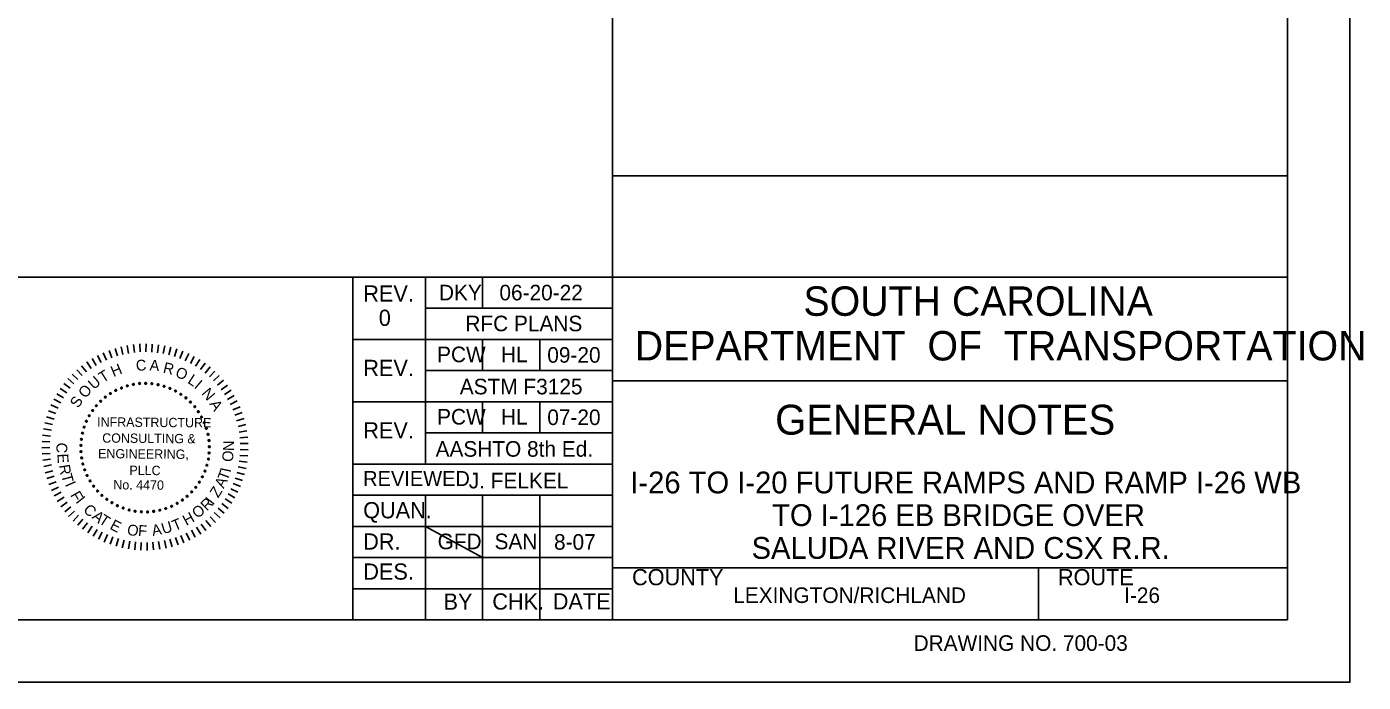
# Model space of a CAD drawing. Extents: x -1.3 to 34.8, y 0.8 to 22.8.
# Drawn here: x 24.06 to 34.78, y 0.82 to 6.08 of the extents above; entities that cross this region are included whole.
import ezdxf

# ---------------------------------------------------------------- set-up
doc = ezdxf.new("R2010")
doc.units = 0
for name, color, linetype in [('BR_BORDER LINES', 7, 'Continuous'), ('BR_TEXT', 7, 'Continuous'), ('Level 31', 7, 'Continuous')]:
    doc.layers.add(name, color=color, linetype=linetype)

msp = doc.modelspace()

# ---------------------------------------------------------------- linework, layer by layer
at = {"layer": 'BR_BORDER LINES'}
for p, q in [((34.177, 1.318), (34.177, 22.318)), ((28.76, 1.318), (28.76, 6.595)), ((28.76, 4.88), (34.177, 4.88)), ((21.311, 4.068), (26.676, 4.068)), ((26.676, 1.318), (26.676, 4.068)), ((26.676, 4.068), (34.177, 4.068)), ((27.26, 4.068), (27.26, 2.568)), ((27.718, 3.818), (27.718, 4.068)), ((27.26, 3.818), (28.76, 3.818)), ((26.676, 3.568), (28.76, 3.568)), ((27.718, 3.318), (27.718, 3.568)), ((28.176, 3.318), (28.176, 3.568)), ((27.26, 3.318), (28.76, 3.318)), ((28.76, 3.235), (28.76, 3.235)), ((28.76, 3.235), (34.177, 3.235)), ((26.676, 3.068), (28.76, 3.068)), ((27.718, 2.818), (27.718, 3.068)), ((28.176, 2.818), (28.176, 3.068)), ((27.26, 2.818), (28.76, 2.818)), ((26.676, 2.568), (28.76, 2.568)), ((26.676, 2.318), (28.76, 2.318)), ((27.26, 2.318), (27.26, 1.318)), ((27.718, 2.318), (27.718, 1.318)), ((28.176, 2.318), (28.176, 1.318)), ((26.676, 2.068), (28.76, 2.068)), ((26.676, 1.818), (28.76, 1.818)), ((28.76, 1.735), (34.177, 1.735)), ((28.857, 1.735), (34.177, 1.735)), ((32.177, 1.318), (32.177, 1.735)), ((26.676, 1.568), (28.76, 1.568)), ((0.511, 1.318), (34.177, 1.318))]:
    msp.add_line(p, q, dxfattribs=at)
at = {"layer": 'BR_TEXT'}
for p, q in [((24.629, 3.439), (24.658, 3.382)), ((24.674, 3.461), (24.7, 3.402)), ((24.721, 3.48), (24.743, 3.42)), ((24.769, 3.496), (24.788, 3.435)), ((24.818, 3.509), (24.832, 3.447)), ((24.867, 3.519), (24.878, 3.456)), ((24.917, 3.526), (24.924, 3.463)), ((24.967, 3.531), (24.971, 3.467)), ((25.018, 3.532), (25.017, 3.468)), ((25.068, 3.53), (25.064, 3.466)), ((25.118, 3.524), (25.11, 3.461)), ((25.168, 3.516), (25.156, 3.454)), ((25.218, 3.505), (25.202, 3.444)), ((25.266, 3.491), (25.246, 3.43)), ((25.313, 3.474), (25.29, 3.415)), ((25.36, 3.454), (25.333, 3.396)), ((24.463, 3.325), (24.505, 3.277)), ((24.501, 3.357), (24.541, 3.307)), ((24.542, 3.387), (24.578, 3.334)), ((24.585, 3.414), (24.618, 3.359)), ((25.405, 3.431), (25.375, 3.375)), ((25.449, 3.406), (25.415, 3.352)), ((25.491, 3.378), (25.454, 3.326)), ((25.531, 3.347), (25.491, 3.298)), ((24.391, 3.254), (24.439, 3.211)), ((24.426, 3.29), (24.471, 3.245)), ((25.569, 3.314), (25.526, 3.267)), ((25.605, 3.279), (25.559, 3.235)), ((25.639, 3.242), (25.591, 3.2)), ((24.301, 3.132), (24.356, 3.099)), ((24.329, 3.174), (24.381, 3.138)), ((24.359, 3.215), (24.409, 3.176)), ((25.671, 3.202), (25.62, 3.164)), ((25.7, 3.161), (25.647, 3.126)), ((25.726, 3.118), (25.671, 3.086)), ((24.255, 3.042), (24.313, 3.016)), ((24.277, 3.088), (24.333, 3.058)), ((25.75, 3.074), (25.693, 3.045)), ((25.772, 3.028), (25.713, 3.003)), ((24.206, 2.899), (24.268, 2.884)), ((24.219, 2.948), (24.28, 2.929)), ((24.235, 2.996), (24.295, 2.973)), ((25.79, 2.981), (25.73, 2.96)), ((25.805, 2.933), (25.744, 2.915)), ((24.188, 2.8), (24.251, 2.793)), ((24.195, 2.85), (24.258, 2.839)), ((25.818, 2.884), (25.756, 2.87)), ((25.827, 2.834), (25.764, 2.824)), ((24.182, 2.699), (24.246, 2.7)), ((24.184, 2.75), (24.247, 2.746)), ((25.834, 2.784), (25.77, 2.778)), ((25.837, 2.734), (25.773, 2.732)), ((25.837, 2.683), (25.774, 2.685)), ((24.184, 2.649), (24.248, 2.653)), ((24.189, 2.598), (24.252, 2.607)), ((25.829, 2.583), (25.766, 2.592)), ((25.835, 2.633), (25.771, 2.638)), ((24.197, 2.549), (24.259, 2.561)), ((24.208, 2.499), (24.27, 2.515)), ((24.222, 2.451), (24.282, 2.47)), ((25.808, 2.484), (25.747, 2.501)), ((25.82, 2.533), (25.758, 2.546)), ((24.239, 2.403), (24.298, 2.426)), ((24.259, 2.357), (24.316, 2.384)), ((25.755, 2.343), (25.697, 2.37)), ((25.775, 2.389), (25.716, 2.413)), ((25.793, 2.436), (25.733, 2.456)), ((24.281, 2.312), (24.337, 2.342)), ((24.306, 2.268), (24.36, 2.302)), ((24.334, 2.226), (24.386, 2.263)), ((25.705, 2.255), (25.652, 2.289)), ((25.731, 2.298), (25.676, 2.329)), ((24.365, 2.186), (24.414, 2.225)), ((24.397, 2.147), (24.445, 2.19)), ((24.433, 2.111), (24.477, 2.157)), ((25.576, 2.1), (25.532, 2.146)), ((25.612, 2.136), (25.565, 2.179)), ((25.645, 2.173), (25.596, 2.214)), ((25.676, 2.213), (25.625, 2.251)), ((24.47, 2.077), (24.511, 2.125)), ((24.509, 2.045), (24.548, 2.096)), ((24.55, 2.016), (24.585, 2.069)), ((24.593, 1.989), (24.625, 2.044)), ((25.457, 2.007), (25.422, 2.061)), ((25.498, 2.036), (25.461, 2.087)), ((25.538, 2.067), (25.497, 2.116)), ((24.637, 1.965), (24.666, 2.022)), ((24.683, 1.943), (24.708, 2.002)), ((24.73, 1.925), (24.751, 1.985)), ((24.778, 1.909), (24.796, 1.971)), ((24.827, 1.897), (24.841, 1.959)), ((24.876, 1.887), (24.887, 1.95)), ((24.927, 1.88), (24.933, 1.944)), ((24.977, 1.877), (24.979, 1.94)), ((25.027, 1.876), (25.026, 1.94)), ((25.078, 1.879), (25.072, 1.942)), ((25.128, 1.885), (25.119, 1.948)), ((25.178, 1.893), (25.165, 1.956)), ((25.227, 1.905), (25.21, 1.967)), ((25.275, 1.92), (25.255, 1.98)), ((25.322, 1.937), (25.298, 1.996)), ((25.369, 1.958), (25.341, 2.015)), ((25.413, 1.981), (25.382, 2.037))]:
    msp.add_line(p, q, dxfattribs=at)
for centre, start, end in [((24.966, 3.214), 5.0653, 185.0653), ((25.015, 3.215), 359.5268, 179.5268), ((25.065, 3.213), 353.9884, 173.9884), ((24.691, 3.105), 38.2961, 218.2961), ((24.732, 3.134), 32.7576, 212.7576), ((24.732, 3.134), 212.7576, 32.7576), ((24.775, 3.159), 27.2191, 207.2191), ((24.775, 3.159), 207.2191, 27.2191), ((24.821, 3.179), 21.6807, 201.6807), ((24.821, 3.179), 201.6807, 21.6807), ((24.868, 3.195), 16.1422, 196.1422), ((24.868, 3.195), 196.1422, 16.1422), ((24.916, 3.207), 10.6038, 190.6038), ((24.916, 3.207), 190.6038, 10.6038), ((24.966, 3.214), 185.0653, 5.0653), ((25.015, 3.215), 179.5268, 359.5268), ((25.065, 3.213), 173.9884, 353.9884), ((25.114, 3.205), 348.4499, 168.4499), ((25.114, 3.205), 168.4499, 348.4499), ((25.163, 3.192), 342.9114, 162.9114), ((25.163, 3.192), 162.9114, 342.9114), ((25.209, 3.175), 157.373, 337.373), ((25.209, 3.175), 337.373, 157.373), ((25.254, 3.154), 151.8345, 331.8345), ((25.254, 3.154), 331.8345, 151.8345), ((25.297, 3.128), 146.2961, 326.2961), ((25.297, 3.128), 326.2961, 146.2961), ((24.589, 2.997), 54.9114, 234.9114), ((24.589, 2.997), 234.9114, 54.9114), ((24.619, 3.036), 49.373, 229.373), ((24.619, 3.036), 229.373, 49.373), ((24.654, 3.072), 43.8345, 223.8345), ((24.654, 3.072), 223.8345, 43.8345), ((24.691, 3.105), 218.2961, 38.2961), ((25.337, 3.099), 140.7576, 320.7576), ((25.337, 3.099), 320.7576, 140.7576), ((25.374, 3.065), 135.2191, 315.2191), ((25.374, 3.065), 315.2191, 135.2191), ((25.408, 3.028), 129.6807, 309.6807), ((25.408, 3.028), 309.6807, 129.6807), ((24.539, 2.911), 65.9884, 245.9884), ((24.539, 2.911), 245.9884, 65.9884), ((24.562, 2.955), 60.4499, 240.4499), ((24.562, 2.955), 240.4499, 60.4499), ((25.437, 2.988), 124.1422, 304.1422), ((25.437, 2.988), 304.1422, 124.1422), ((25.463, 2.946), 118.6038, 298.6038), ((25.463, 2.946), 298.6038, 118.6038), ((25.485, 2.901), 113.0653, 293.0653), ((25.485, 2.901), 293.0653, 113.0653), ((24.508, 2.816), 77.0653, 257.0653), ((24.508, 2.816), 257.0653, 77.0653), ((24.521, 2.864), 71.5268, 251.5268), ((24.521, 2.864), 251.5268, 71.5268), ((25.502, 2.854), 107.5268, 287.5268), ((25.502, 2.854), 287.5268, 107.5268), ((25.515, 2.806), 101.9884, 281.9884), ((25.515, 2.806), 281.9884, 101.9884), ((24.495, 2.718), 88.1422, 268.1422), ((24.499, 2.767), 82.6038, 262.6038), ((24.495, 2.718), 268.1422, 88.1422), ((24.499, 2.767), 262.6038, 82.6038), ((25.523, 2.757), 96.4499, 276.4499), ((25.526, 2.707), 90.9114, 270.9114), ((25.523, 2.757), 276.4499, 96.4499), ((25.526, 2.707), 270.9114, 90.9114), ((24.495, 2.668), 93.6807, 273.6807), ((24.501, 2.618), 99.2191, 279.2191), ((24.495, 2.668), 273.6807, 93.6807), ((24.501, 2.618), 279.2191, 99.2191), ((24.511, 2.569), 104.7576, 284.7576), ((24.511, 2.569), 284.7576, 104.7576), ((25.518, 2.608), 79.8345, 259.8345), ((25.518, 2.608), 259.8345, 79.8345), ((25.524, 2.657), 85.373, 265.373), ((25.524, 2.657), 265.373, 85.373), ((24.526, 2.522), 110.2961, 290.2961), ((24.526, 2.522), 290.2961, 110.2961), ((24.545, 2.476), 115.8345, 295.8345), ((24.545, 2.476), 295.8345, 115.8345), ((25.47, 2.466), 63.2191, 243.2191), ((25.47, 2.466), 243.2191, 63.2191), ((25.49, 2.512), 68.7576, 248.7576), ((25.49, 2.512), 248.7576, 68.7576), ((25.506, 2.559), 74.2961, 254.2961), ((25.506, 2.559), 254.2961, 74.2961), ((24.569, 2.432), 121.373, 301.373), ((24.569, 2.432), 301.373, 121.373), ((24.597, 2.391), 126.9114, 306.9114), ((24.597, 2.391), 306.9114, 126.9114), ((24.629, 2.352), 312.4499, 132.4499), ((25.417, 2.382), 52.1422, 232.1422), ((25.417, 2.382), 232.1422, 52.1422), ((25.445, 2.423), 57.6807, 237.6807), ((25.445, 2.423), 237.6807, 57.6807), ((24.629, 2.352), 132.4499, 312.4499), ((24.664, 2.317), 137.9884, 317.9884), ((24.664, 2.317), 317.9884, 137.9884), ((24.703, 2.286), 143.5268, 323.5268), ((24.703, 2.286), 323.5268, 143.5268), ((24.744, 2.258), 149.0653, 329.0653), ((24.744, 2.258), 329.0653, 149.0653), ((25.267, 2.253), 29.9884, 209.9884), ((25.267, 2.253), 209.9884, 29.9884), ((25.309, 2.279), 35.5268, 215.5268), ((25.309, 2.279), 215.5268, 35.5268), ((25.348, 2.31), 41.0653, 221.0653), ((25.348, 2.31), 221.0653, 41.0653), ((25.384, 2.345), 46.6038, 226.6038), ((25.384, 2.345), 226.6038, 46.6038), ((24.788, 2.234), 154.6038, 334.6038), ((24.788, 2.234), 334.6038, 154.6038), ((24.834, 2.215), 340.1422, 160.1422), ((24.834, 2.215), 160.1422, 340.1422), ((24.882, 2.2), 345.6807, 165.6807), ((24.882, 2.2), 165.6807, 345.6807), ((24.93, 2.19), 351.2191, 171.2191), ((24.93, 2.19), 171.2191, 351.2191), ((24.98, 2.185), 356.7576, 176.7576), ((24.98, 2.185), 176.7576, 356.7576), ((25.03, 2.184), 2.2961, 182.2961), ((25.03, 2.184), 182.2961, 2.2961), ((25.079, 2.189), 7.8345, 187.8345), ((25.079, 2.189), 187.8345, 7.8345), ((25.128, 2.198), 13.373, 193.373), ((25.128, 2.198), 193.373, 13.373), ((25.176, 2.212), 18.9114, 198.9114), ((25.176, 2.212), 198.9114, 18.9114), ((25.223, 2.23), 24.4499, 204.4499), ((25.223, 2.23), 204.4499, 24.4499)]:
    msp.add_arc(centre, 0.00701, start, end, dxfattribs=at)
at = {"layer": 'Level 31'}
for p, q in [((31.468, 2.795), (31.468, 2.795)), ((27.26, 2.068), (27.718, 1.818))]:
    msp.add_line(p, q, dxfattribs=at)
msp.add_lwpolyline([(-1.323, 0.818), (34.677, 0.818), (34.677, 22.818), (-1.323, 22.818)], close=True, dxfattribs=at)

# ---------------------------------------------------------------- texts
at = {"layer": 'BR_TEXT'}
for s, height, p in [('REV.', 0.13, (26.761, 3.871)), ('DKY', 0.125, (27.368, 3.881)), ('06-20-22', 0.125, (27.853, 3.881)), ('SOUTH CAROLINA', 0.23587, (30.292, 3.757)), ('0', 0.13, (26.885, 3.676)), ('RFC PLANS', 0.125, (27.58, 3.633)), ('DEPARTMENT  OF  TRANSPORTATION', 0.23587, (28.939, 3.399)), ('PCW', 0.125, (27.353, 3.385)), ('HL', 0.125, (27.866, 3.385)), ('09-20', 0.125, (28.237, 3.381)), ('REV.', 0.13, (26.761, 3.274)), ('ASTM F3125', 0.125, (27.535, 3.127)), ('PCW', 0.125, (27.353, 2.885)), ('HL', 0.125, (27.866, 2.885)), ('07-20', 0.125, (28.237, 2.881)), ('GENERAL NOTES', 0.24, (30.065, 2.804)), ('REV.', 0.13, (26.761, 2.774)), ('AASHTO 8th Ed.', 0.125, (27.341, 2.627)), ('REVIEWED', 0.12, (26.76, 2.392)), ('J. FELKEL', 0.125, (27.607, 2.373)), ('I-26 TO I-20 FUTURE RAMPS AND RAMP I-26 WB', 0.175, (28.903, 2.333)), ('QUAN.', 0.13, (26.76, 2.133)), ('TO I-126 EB BRIDGE OVER', 0.175, (30.041, 2.071)), ('DR.', 0.13, (26.76, 1.882)), ('GFD', 0.125, (27.357, 1.885)), ('SAN', 0.125, (27.814, 1.885)), ('8-07', 0.125, (28.291, 1.881)), ('SALUDA RIVER AND CSX R.R.', 0.175, (29.876, 1.808)), ('DES.', 0.13, (26.761, 1.641)), ('COUNTY', 0.13, (28.917, 1.596)), ('ROUTE', 0.13, (32.334, 1.596)), ('BY', 0.13, (27.405, 1.4)), ('CHK.', 0.13, (27.796, 1.401)), ('DATE', 0.13, (28.281, 1.402)), ('LEXINGTON/RICHLAND', 0.12499, (29.729, 1.454)), ('I-26', 0.125, (32.865, 1.454)), ('DRAWING NO. 700-03', 0.125, (31.176, 1.07))]:
    msp.add_text(s, height=height, dxfattribs=at).set_placement(p)
for s, height, rotation, p in [('T', 0.0872, 31.8182, (24.672, 3.217)), ('H', 0.0872, 22.7882, (24.757, 3.265)), ('C', 0.0872, 4.7281, (24.94, 3.314)), ('A', 0.0872, 355.6981, (25.044, 3.319)), ('R', 0.0872, 346.6681, (25.149, 3.302)), ('O', 0.0872, 337.638, (25.246, 3.272)), ('U', 0.0872, 40.8482, (24.599, 3.161)), ('L', 0.0872, 327.108, (25.345, 3.222)), ('I', 0.0872, 319.578, (25.398, 3.184)), ('S', 0.0872, 58.9083, (24.476, 3.012)), ('O', 0.0872, 49.8782, (24.532, 3.09)), ('N', 0.0872, 310.548, (25.459, 3.133)), ('A', 0.0872, 301.5179, (25.524, 3.051)), ('INFRASTRUCTURE', 0.07477, 359.5268, (24.625, 2.869)), ('CONSULTING &', 0.07477, 359.5268, (24.666, 2.74)), ('C', 0.0872, 267.025, (24.301, 2.742)), ('ENGINEERING,', 0.07477, 359.5268, (24.633, 2.615)), ('N', 0.0872, 89.2085, (25.723, 2.672)), ('E', 0.0872, 273.025, (24.306, 2.65)), ('O', 0.0872, 83.2085, (25.712, 2.581)), ('R', 0.0872, 279.025, (24.319, 2.558)), ('T', 0.0872, 285.025, (24.336, 2.479)), ('PLLC', 0.0748, 359.5268, (24.884, 2.481)), ('T', 0.0872, 69.3954, (25.671, 2.429)), ('I', 0.0872, 77.9093, (25.696, 2.496)), ('I', 0.0872, 293.7713, (24.366, 2.406)), ('No. 4470', 0.0748, 359.5268, (24.755, 2.365)), ('Z', 0.0872, 57.3954, (25.596, 2.292)), ('A', 0.0872, 63.3954, (25.64, 2.368)), ('F', 0.0872, 299.7713, (24.407, 2.32)), ('I', 0.0872, 308.5268, (24.449, 2.266)), ('R', 0.0872, 44.5268, (25.506, 2.187)), ('I', 0.0872, 52.3339, (25.555, 2.234)), ('C', 0.0872, 314.5268, (24.508, 2.196)), ('A', 0.0872, 320.5268, (24.578, 2.137)), ('T', 0.0872, 326.5268, (24.632, 2.099)), ('H', 0.0872, 28.5268, (25.341, 2.071)), ('O', 0.0872, 38.5268, (25.429, 2.127)), ('E', 0.0872, 332.5268, (24.721, 2.051)), ('O', 0.0872, 350.5268, (24.861, 2.002)), ('F', 0.0872, 356.5268, (24.952, 1.993)), ('A', 0.0872, 10.5268, (25.072, 1.991)), ('U', 0.0872, 16.5268, (25.156, 2.005)), ('T', 0.0872, 22.5268, (25.248, 2.029))]:
    msp.add_text(s, height=height, rotation=rotation, dxfattribs=at).set_placement(p)

doc.saveas('drawing.dxf')
